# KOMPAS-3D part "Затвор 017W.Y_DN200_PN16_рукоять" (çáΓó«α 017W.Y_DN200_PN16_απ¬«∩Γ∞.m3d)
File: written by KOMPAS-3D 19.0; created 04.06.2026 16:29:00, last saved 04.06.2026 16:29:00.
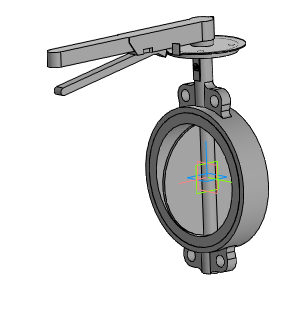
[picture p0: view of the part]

Document properties: Автор: Энергия; Полное имя файла: ..\..\..\3d для проектировщиков\017W разные\x.x Тип 017W.Y(S) Затвор дисковый поворотный межфланцевый\Затвор 017W.Y(S)_DN32-DN350_рукоять\Затвор 017W.Y_DN200_PN16_рукоять.a3d

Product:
- Part/product: Затвор 017W.Y_DN200_PN16_рукоять
    Масса: 18.189

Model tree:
1. Операция без истории:1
